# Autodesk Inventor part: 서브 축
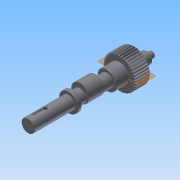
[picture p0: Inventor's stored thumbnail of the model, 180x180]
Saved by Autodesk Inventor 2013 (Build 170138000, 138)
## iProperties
Created: 2016-02
Part Number: 서브 축
Material: 강철, 연강
Document SubType Name: Modeling
Designer: mdu
Categories: <?xml version="1.0" encoding="UTF-16"?> <MemberInstance><Categories><FamilyTemplate><FamilyTemplateParameter ValueType="xs:double" Id="1" ObjectReferenceKey="da
Density: 7.86 g/cm^3
Mass: 506.173 g
Surface Area: 164.116 cm^2
Volume: 64.3986 cm^3
CustomPartVersion: 1
Author: mdu
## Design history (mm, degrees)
sketch "Sketch1"
  geometry: C1 r 21 at (0, 0)
  constraints: 1 centre point
  dimensions: "d0" = 42 diameter of C1 (= da_da)
extrude "Extrusion1" new body sketch "Sketch1" distance "d1" = 20 (= da_b); taper "d2" = 0 deg
workplane "Work Plane2"
feature "피치 지름" dims "d4" = 10, "d5" = 0
workplane "Work Plane8"
workplane "Work Plane9"
chamfer "모따기1" distance "d49" = 1; stored, may be unused: second distance "d50" = 2, angle "d51" = 45 deg
sketch "스케치3"
  geometry: C1 r 12.5 at (0, 0); 1 further point
  constraints: 1 centre point, 1 coincident
  dimensions: "d52" = 25 diameter of C1
extrude "돌출2" join sketch "스케치3" distance "d53" = 16; taper "d54" = 0 deg
sketch "스케치4"
  geometry: C1 r 8.5 at (0, 0); 1 further point
  constraints: 1 centre point, 1 coincident
  dimensions: "d55" = 17 diameter of C1
extrude "돌출3" join sketch "스케치4" distance "d56" = 103; taper "d57" = 0 deg
sketch "스케치5"
  geometry: C1 r 7.5 at (0, 0); 1 further point
  constraints: 1 centre point, 1 coincident
  dimensions: "d62" = 15 diameter of C1
extrude "돌출4" join sketch "스케치5" distance "d63" = 16; taper "d64" = 0 deg
sketch "스케치6"
  geometry: C1 r 4 at (0, 0); 1 further point
  constraints: 1 centre point, 1 coincident
  dimensions: "d65" = 8 diameter of C1
extrude "돌출5" join sketch "스케치6" distance "d66" = 7; taper "d67" = 0 deg
chamfer "모따기2" distance "d58" = 0.5; stored, may be unused: second distance "d59" = 2, angle "d60" = 45 deg
fillet "모깎기1" dims "d61" = 0.5
feature "스퍼 기어" dims "da_b" = 20, "da_d" = 40, "da_aw" = 31, "da_da" = 42, "da_df" = 37.5, "da_dw" = 40, angle "da_beta" = 0 deg, "da_lefttooth" = 0, "da_righttooth" = 0
node "작업 평면11"
sketch "스케치7"
  geometry: C1 r 8.5 at (0, 0) reference; C2 r 11.5 at (0, 3); 1 further point
  constraints: 1 centre point, 1 tangent, 1 vertical alignment
  dimensions: "d71" = 3 distance of C2.centre point (0, 0); "d72" = 23 diameter of C2 (derived)
extrude "돌출6" join sketch "스케치7" stored distance "d73" = 20; taper "d74" = 0 deg
node "작업 평면12"
sketch "스케치8"
  geometry: C1 r 12.5 at (0, 0) reference; 1 further point
extrude "돌출7" join sketch "스케치8" distance "d76" = 5; taper "d77" = 0 deg
chamfer "모따기3" distance "d78" = 0.5; stored, may be unused: second distance "d79" = 2, angle "d80" = 45 deg
sketch "스케치9"
  geometry: L1 (-8.5, 86)-(-8.5, 138.5) reference; L2 (-8, 139)-(8, 139) reference; L3 (0, 0)-(0, 139); L4 (-8.5, 115)-(0, 115); L5 (-8.5, 115)-(-8.5, 113.5); L6 (-7, 115)-(-8.5, 113.5)
  constraints: 8 end point, 4 point on line, 1 midpoint, 1 perpendicular
  dimensions: "d81" = 24 distance between parallel lines of L2 L4; "d82" = 45 deg angle of L6 L5; "d83" = 3 diameter of L5.end L4
revolve "회전1" sketch "스케치9" stored, may be unused: angle "d84" = 90 deg
sketch "스케치10"
  geometry: L1 (-8.5, 113.5)-(-7, 115) reference; L2 (-8.5, 116.5)-(-7, 115) reference; 2 further points
  constraints: 1 coincident
node "작업점1"
node "작업 평면14"
sketch "스케치11"
  geometry: L1 (8.5, 102.5)-(-8.5, 102.5) reference; L2 (0, 102.5)-(0, -36); L3 (-2.5, 93.5)-(-2.5, 80.5); L4 (2.5, 80.5)-(2.5, 93.5); L5 (-8, 103)-(8, 103) reference; A1 r 2.5 centre (0, 93.5) between (2.5, 93.5) and (-2.5, 93.5); A2 r 2.5 centre (0, 80.5) between (-2.5, 80.5) and (2.5, 80.5)
  constraints: 6 end point, 4 point on circle, 4 tangent, 2 centre point, 1 midpoint, 1 parallel, 1 perpendicular, 1 point on line, 1 vertical alignment
  dimensions: "d85" = 7 distance edge to line of A1 L5; "d86" = 18 dimension on A2 A1; "d87" = 5 distance between parallel lines of L3 L4
extrude "돌출8" cut sketch "스케치11" distance "d88" = 3; taper "d89" = 0 deg
body "Solid1"
sketch "Sketch2"
  geometry: C1 r 21 at (0, 0) reference; C2 r 20 at (0, 0)
  constraints: 1 centre point, 1 coincident
  dimensions: "d3" = 40 diameter of C2 (= da_dw)
body "Srf1"
other parameters: "d16" = 31 (= da_aw), "d17" = 0, "d34" = 4.5 deg (computed from da_z), "d39" = 0, "d41" = 0, "d43" = 31 (= da_aw), "d46" = 31 (= da_aw), "d47" = 0, "d48" = 0, "d68" = 25
